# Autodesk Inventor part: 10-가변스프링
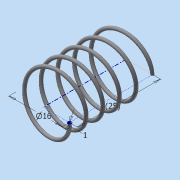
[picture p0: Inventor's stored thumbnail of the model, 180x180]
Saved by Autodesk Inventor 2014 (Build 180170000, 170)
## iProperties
Created: 2015-06
Part Number: 10-가변스프링
Material: 강철, 연강
Document SubType Name: Modeling
Designer: Administrator
Density: 7.86 g/cm^3
Appearance: 강철
Mass: 1.52988 g
Surface Area: 7.87024 cm^2
Volume: 0.194641 cm^3
Author: Administrator
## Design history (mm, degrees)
sketch "스케치1"
  geometry: L1 (0, 0)-(8, 0); L2 (8, 0)-(8, 14.5); L3 (8, 14.5)-(0, 14.5); L4 (0, 14.5)-(0, 0); C1 r 0.5 at (8, 0)
  constraints: 8 end point, 2 parallel, 1 centre point, 1 coincident, 1 horizontal, 1 perpendicular
  dimensions: "d0" = 1 diameter of C1; "d1" = 16 diameter of L2 L4; "d2" = 14.5 distance of L1.end L2.end (derived)
feature "코일1" sketch "스케치1" pitch "d3" = 10; turns "d5" = 5; dims "d4" = 14.5 (= d2), "d6" = 0, angle "d7" = 90 deg, angle "d8" = 90 deg, "d9" = 0, "d10" = 0
sketch "스케치2"
  geometry: L1 (-8.5, 0)-(-7.5, 0) reference; 1 further point
  constraints: 1 horizontal alignment
extrude "돌출1" cut sketch "스케치2" distance "d11" = 10; taper "d12" = 0 deg
node "작업 평면1"
sketch "스케치3"
  geometry: L1 (-7.5, 0)-(-8.5, 0) reference; 1 further point
  constraints: 1 horizontal alignment
extrude "돌출2" cut sketch "스케치3" distance "d14" = 10; taper "d15" = 0 deg
node "솔리드1"
node "절단 모서리 투영1"
node "절단 모서리 투영2"
other parameters: "d13" = 14.5 (= d2)
